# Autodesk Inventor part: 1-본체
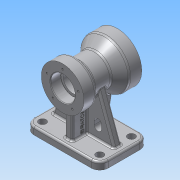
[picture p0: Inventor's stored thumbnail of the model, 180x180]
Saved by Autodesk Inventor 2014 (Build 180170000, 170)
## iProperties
Created: 2015-08
Part Number: 1-본체
Material: 알루미늄 6061
Document SubType Name: Modeling
Designer: SDA16
Density: 2.71 g/cm^3
Appearance: 알루미늄 - 평지
Mass: 1062.79 g
Surface Area: 749.652 cm^2
Volume: 392.172 cm^3
Author: SDA16
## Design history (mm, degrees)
sketch "스케치1"
  geometry: L1 (61, -40)-(-61, -40); L2 (-61, -40)-(-61, 40); L3 (-61, 40)-(61, 40); L4 (61, 40)-(61, -40); L5 (61, -40)-(-61, 40); L6 (-61, -40)-(61, 40); 1 further point
  constraints: 12 end point, 2 midpoint, 2 parallel, 1 horizontal, 1 perpendicular
  dimensions: "d0" = 122 distance of L1.start L1.end; "d1" = 80 distance of L3.end L1.start
extrude "돌출1" new body sketch "스케치1" distance "d2" = 12; taper "d3" = 0 deg
sketch "스케치2"
  geometry: L1 (-40, 0)-(-40, 12) reference; L2 (40, 0)-(-40, 0) reference; L3 (-40, 90)-(50, 90); L4 (-40, 90)-(-40, 125); L5 (-40, 125)-(-20, 125); L6 (-20, 125)-(-14.804, 116); L7 (-14.804, 116)-(13.315, 116); L8 (13.315, 116)-(30, 130); L9 (30, 130)-(50, 130); L10 (50, 130)-(50, 90); 1 further point
  constraints: 16 end point, 4 parallel, 2 perpendicular, 1 vertical alignment
  dimensions: "d4" = 90 distance of L3.start L3.end; "d5" = 90 distance between parallel lines of L2 L3; "d6" = 20 distance of L4.end L5.end; "d7" = 20 distance of L8.end L9.end; "d8" = 60 deg angle of L7 L6; "d9" = 40 deg angle of L8 L7; "d10" = 70 diameter of L5 L3; "d11" = 80 diameter of L9 L3; "d12" = 52 diameter of L7 L3
revolve "회전1" sketch "스케치2" stored, may be unused: angle "d13" = 90 deg
sketch "스케치3"
  geometry: L1 (-61, 12)-(61, 12) reference; L2 (-21.331, 93.514)-(-51, 12); L3 (51, 12)-(21.331, 93.514); L4 (21.331, 93.514)-(-21.331, 93.514); L5 (61, 0)-(-61, 0) reference; L6 (61, 0)-(61, 12) reference; 3 further points
  constraints: 6 end point, 2 midpoint, 2 point on line, 1 equal length, 1 parallel, 1 vertical alignment
  dimensions: "d14" = 70 deg angle of L1 L3; "d15" = 10 distance from line of L3.start L6; "d16" = 42.66233 distance of L3.end L2.start
extrude "돌출2" join sketch "스케치3" stored distance "d17" = 12; taper "d18" = 0 deg
sketch "스케치4"
  geometry: L1 (-40, 12)-(40, 12) reference; L2 (-30, 12)-(-30, 98.4); L3 (-30, 98.4)-(38.921, 98.4); L4 (38.921, 98.4)-(38.921, 62.592); L5 (38.921, 62.592)-(30, 12); L6 (-40, 0)-(-40, 12) reference; 1 further point
  constraints: 8 end point, 2 perpendicular, 2 point on line, 1 parallel
  dimensions: "d19" = 80 deg angle of L1 L5; "d20" = 10 distance of L5.end L1.end; "d21" = 10 distance between parallel lines of L2 L6; "d22" = 68.92069 distance of L2.end L3.end; "d23" = 35.80857 distance of L3.end L4.end
extrude "돌출3" join sketch "스케치4" stored distance "d24" = 12; taper "d25" = 0 deg
hole "구멍1" diameter "d28" = 38; stored, may be unused: countersink angle "d32" = 90 deg, drill point angle "d34" = 0 deg; dims "d29" = 6, "d30" = 52, "d31" = 20, "d33" = 23, "d35" = 10, "d36" = 10
hole "구멍2" diameter "d39" = 32; stored, may be unused: countersink angle "d43" = 90 deg, drill point angle "d45" = 0 deg; dims "d37" = 10, "d38" = 10, "d40" = 6, "d41" = 40, "d42" = 17, "d44" = 23
sketch "스케치5"
  geometry: C1 r 26 at (0, 0) reference; 2 further points
  constraints: 1 vertical alignment
  dimensions: "d47" = 33 distance of point (0, -33) C1.centre
hole "구멍3" sketch "스케치5" at (0, -33) diameter "d48" = 3.242; stored, may be unused: countersink angle "d52" = 90 deg, drill point angle "d54" = 118 deg; dims "d49" = 10, "d50" = 40, "d51" = 17, "d53" = 13
sketch "스케치6"
  geometry: C1 r 20 at (0, 0) reference; 2 further points
  constraints: 1 vertical alignment
  dimensions: "d58" = 27 distance of C1.centre point (0, 27)
hole "구멍4" sketch "스케치6" at (0, 27) diameter "d59" = 3.242; stored, may be unused: countersink angle "d63" = 90 deg, drill point angle "d65" = 118 deg; dims "d60" = 10, "d61" = 40, "d62" = 17, "d64" = 13
sketch "스케치7"
  geometry: L1 (-6, 12)-(-51, 12) reference; L2 (-30, 36)-(-30, 30); L3 (-18, 30)-(-18, 36); L4 (18, 36)-(18, 30); L5 (30, 30)-(30, 36); L6 (-61, 12)-(61, 12) reference; A1 r 6 centre (-24, 30) between (-30, 30) and (-18, 30); A2 r 6 centre (-24, 36) between (-18, 36) and (-30, 36); A3 r 6 centre (24, 30) between (18, 30) and (30, 30); A4 r 6 centre (24, 36) between (30, 36) and (18, 36); 2 further points
  constraints: 8 end point, 8 point on circle, 8 tangent, 4 centre point, 4 parallel, 2 horizontal alignment, 1 coincident, 1 equal radius, 1 perpendicular
  dimensions: "d69" = 48 distance of A3.centre A1.centre; "d70" = 18 distance from line of L1 A1.centre; "d72" = 12 distance between parallel lines of L3 L2; "d73" = 24 horizontal distance of point (0, 0) A1.centre; "d76" = 6 distance of A1.centre A2.centre
extrude "돌출4" cut sketch "스케치7" stored distance "d74" = 12; taper "d75" = 0 deg
sketch "스케치8"
  geometry: L1 (47, -26)-(-47, -26); L2 (-47, -26)-(-47, 26); L3 (-47, 26)-(47, 26); L4 (47, 26)-(47, -26); L5 (47, -26)-(-47, 26); L6 (-47, -26)-(47, 26); 5 further points
  constraints: 12 end point, 4 coincident, 2 midpoint, 2 parallel, 1 horizontal, 1 perpendicular
  dimensions: "d77" = 94 distance of L2.end L3.end; "d78" = 52 distance of L3.end L1.start
hole "구멍5" sketch "스케치8" at (-47, 26), (-47, -26), (47, -26), (47, 26) diameter "d79" = 12; stored, may be unused: countersink angle "d83" = 90 deg, drill point angle "d85" = 0 deg; dims "d80" = 12, "d81" = 40, "d82" = 17, "d84" = 13
sketch "스케치9"
  geometry: L1 (-55.518, -30)-(-12, -30) reference; L2 (-12, -6)-(-12, -30) reference; 2 further points
  constraints: 1 other
  dimensions: "d86" = 16 distance from line of point (-36, -14) L1; "d87" = 24 distance from line of point (-36, -14) L2
feature "엠보싱1" sketch "스케치9" dims "d88" = 0.5, "d89" = 0
fillet "모깎기1" dims "d90" = 5, "d91" = 0.3, "d92" = 14
fillet "모깎기2" dims "d93" = 3
fillet "모깎기3" dims "d94" = 3
chamfer "모따기1" distance "d95" = 1; stored, may be unused: second distance "d96" = 2, angle "d97" = 45 deg
node "솔리드1"
pattern_circular "원형 패턴1" dims angle "d56" = 360 deg
pattern_circular "원형 패턴2" dims angle "d67" = 360 deg
